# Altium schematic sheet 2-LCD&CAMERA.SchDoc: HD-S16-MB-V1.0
size A4
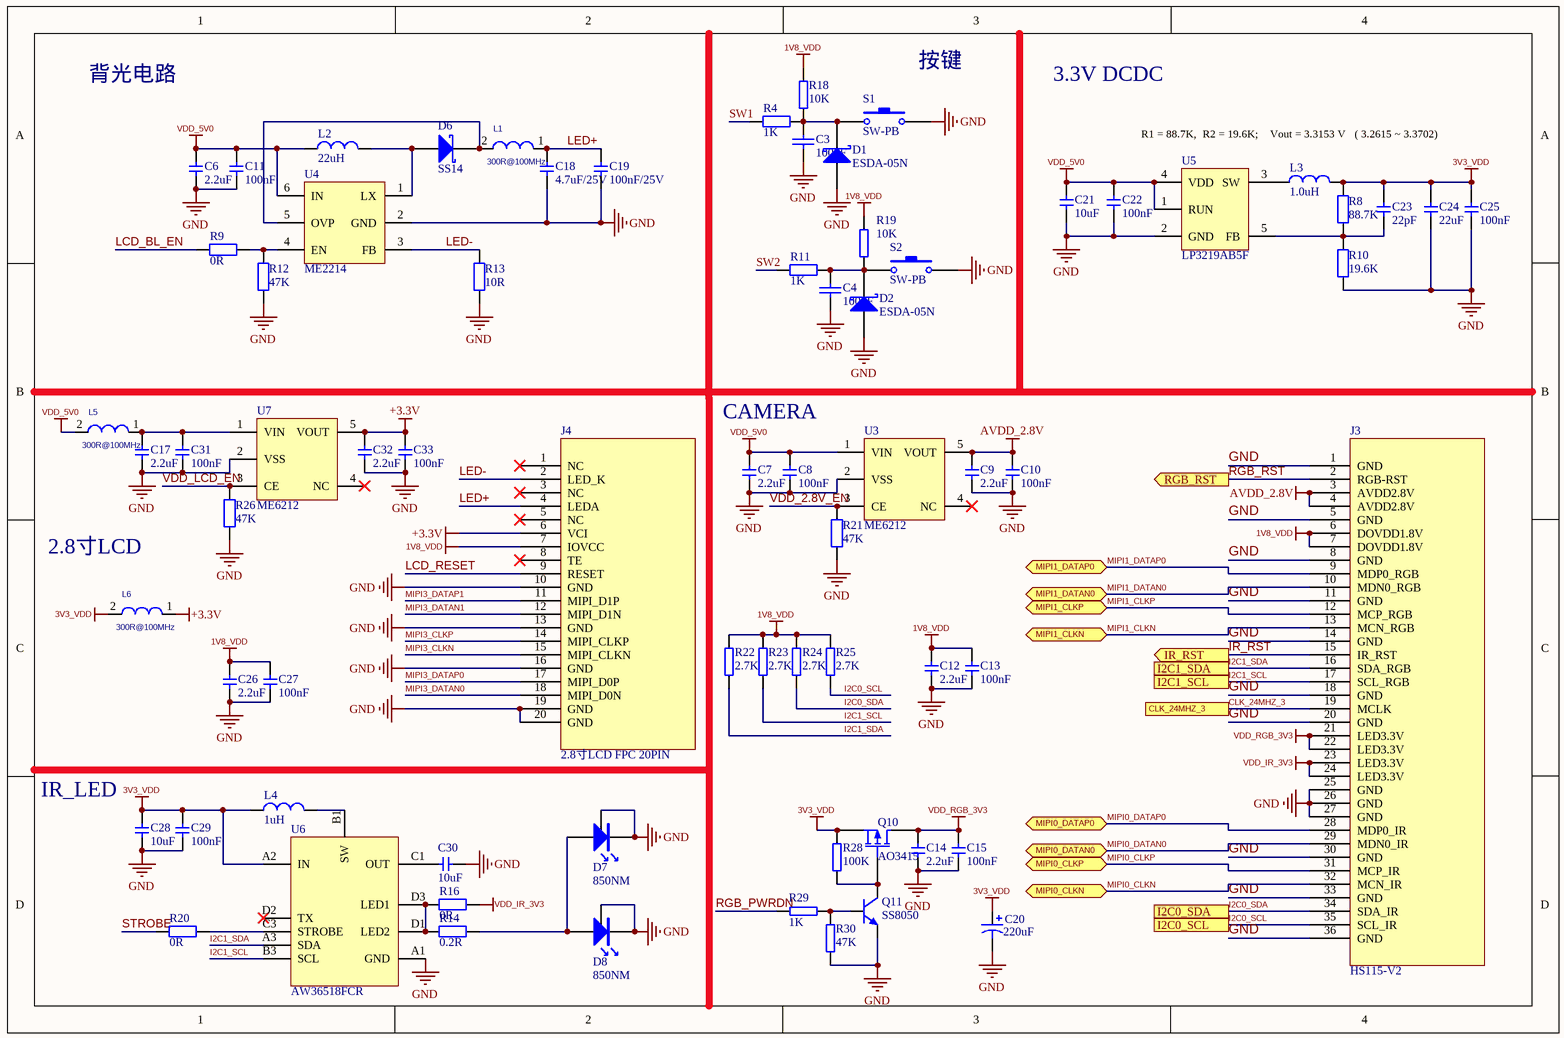
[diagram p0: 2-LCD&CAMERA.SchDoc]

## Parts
C3  100nF  [C0402]
C4  100nF  [C0402]
C6  2.2uF  [C0402]
C7  2.2uF  [C0402]
C8  100nF  [C0402]
C9  2.2uF  [C0402]
C10  100nF  [C0402]
C11  100nF  [C0402]
C12  2.2uF  [C0402]
C13  100nF  [C0402]
C14  2.2uF  [C0402]
C15  100nF  [C0402]
C17  2.2uF  [C0402]
C18  4.7uF/25V  [Cap_0603]
C19  100nF/25V  [C0402]
C20  value 220uF  [SMD,6.3x7.7mm]  (hidden comment: Cap Pol1)
C21  10uF  [Cap_0603]
C22  100nF  [C0402]
C23  22pF  [C0402]
C24  22uF  [CAP_0603]
C25  100nF  [C0402]
C26  2.2uF  [C0402]
C27  100nF  [C0402]
C28  10uF  [C0402]
C29  100nF  [C0402]
C30  10uF  [C0402]
C31  100nF  [C0402]
C32  2.2uF  [C0402]
C33  100nF  [C0402]
D1  ESDA-05N  [R0402]
D2  ESDA-05N  [R0402]
D6  SS14  [SOD-123F]
D7  850NM  [LED-3535-850MM]
D8  850NM  [LED-3535-850MM]
J3  HS115-V2  [0.5-36PIN]
J4  2.8寸LCD FPC 20PIN  [0.5-20PIN-抽屉上接]
L1  300R@100MHz  [Res_0603]
L2  22uH  [L3*3]
L3  1.0uH  [L2.5x2.0x1.0mm]
L4  1uH  [L2.5x2.0x1.0mm]
L5  300R@100MHz  [Res_0603]
L6  300R@100MHz  [Res_0603]
Q10  AO3415  [SOT-23]
Q11  SS8050  [SOT23-BEC]
R4  1K  [R0402]
R8  88.7K  [R0402]
R9  0R  [R0402]
R10  19.6K  [R0402]
R11  1K  [R0402]
R12  47K  [R0402]
R13  10R  [R0805]
R14  0.2R  [R0805]
R16  0R  [R0805]
R18  10K  [R0402]
R19  10K  [R0402]
R20  0R  [R0402]
R21  47K  [R0402]
R22  2.7K  [R0402]
R23  2.7K  [R0402]
R24  2.7K  [R0402]
R25  2.7K  [R0402]
R26  47K  [R0402]
R28  100K  [R0402]
R29  1K  [R0402]
R30  47K  [R0402]
S1  SW-PB  [轻触开关4.5x4.5]
S2  SW-PB  [轻触开关4.5x4.5]
U3  ME6212  [SOT23-5]
U4  ME2214  [SOT26]
U5  LP3219AB5F  [SOT23-5]
U6  AW36518FCR  [FCQFN-10L]
U7  ME6212  [SOT23-5]

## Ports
CLK_24MHZ_3, I2C0_SCL, I2C0_SDA, I2C1_SCL, I2C1_SDA, IR_RST (out), MIPI0_CLKN (bidir), MIPI0_CLKP (bidir), MIPI0_DATAN0 (bidir), MIPI0_DATAP0 (bidir), MIPI1_CLKN (bidir), MIPI1_CLKP (bidir), MIPI1_DATAN0 (bidir), MIPI1_DATAP0 (bidir), RGB_RST (out)

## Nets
1V8_VDD: C12.1 C13.1 C26.1 C27.1 J3.6(DOVDD1.8V) J3.7(DOVDD1.8V) J4.7(IOVCC) R18.2 R19.2 R22.1 R23.1 R24.1 R25.1
3V3_VDD: C20.1 C23.2 C24.1 C25.1 C28.1 C29.1 L3.2 L4.1 L6.2 Q10.2(S) R8.2 R28.2 U6.A2(IN)
+3.3V: C32.1 C33.1 J4.6(VCI) L6.1 U7.5(VOUT)
AVDD_2.8V: C9.1 C10.1 J3.3(AVDD2.8V) J3.4(AVDD2.8V) U3.5(VOUT)
GND: C3.2 C4.2 C6.2 C7.2 C8.2 C9.2 C10.2 C11.2 C12.2 C13.2 C14.2 C15.2 C17.2 C18.2 C19.2 C20.2 C21.2 C22.2 C24.2 C25.2 C26.2 C27.2 C28.2 C29.2 C30.2 C31.2 C32.2 C33.2 D1.1(A) D2.1(A) D7.0 D7.K D8.0 D8.K J3.1(GND) J3.5(GND) J3.8(GND) J3.11(GND) J3.14(GND) J3.18(GND) J3.20(GND) J3.25(GND) J3.26(GND) J3.27(GND) J3.30(GND) J3.33(GND) J3.36(GND) J4.10(GND) J4.13(GND) J4.16(GND) J4.19(GND) J4.20(GND) Q11.E R10.2 R12.1 R13.2 R21.1 R26.1 R30.2 S1.2 S2.2 U3.2(VSS) U4.2(GND) U5.2(GND) U6.A1(GND) U7.2(VSS)
VDD_5V0: C6.1 C7.1 C8.1 C11.1 C21.1 C22.1 L2.1 L5.2 U3.1(VIN) U4.6(IN) U5.1(RUN) U5.4(VDD)
VDD_IR_3V3: J3.23(LED3.3V) J3.24(LED3.3V) R16.2
VDD_RGB_3V3: C14.1 C15.1 J3.21(LED3.3V) J3.22(LED3.3V) Q10.3(D)
CLK_24MHZ_3: J3.19(MCLK) ; port CLK_24MHZ_3
I2C0_SCL: J3.35(SCL_IR) R25.2 ; port I2C0_SCL
I2C0_SDA: J3.34(SDA_IR) R24.2 ; port I2C0_SDA
I2C1_SCL: J3.17(SCL_RGB) R23.2 U6.B3(SCL) ; port I2C1_SCL
I2C1_SDA: J3.16(SDA_RGB) R22.2 U6.A3(SDA) ; port I2C1_SDA
IR_RST: J3.15(IR_RST) ; port IR_RST
LCD_BL_EN: R9.1
LCD_RESET: J4.9(RESET)
LED+: C18.1 C19.1 J4.4(LEDA) L1.1
LED-: J4.2(LED_K) R13.1 U4.3(FB)
MIPI0_CLKN: J3.32(MCN_IR) ; port MIPI0_CLKN
MIPI0_CLKP: J3.31(MCP_IR) ; port MIPI0_CLKP
MIPI0_DATAN0: J3.29(MDN0_IR) ; port MIPI0_DATAN0
MIPI0_DATAP0: J3.28(MDP0_IR) ; port MIPI0_DATAP0
MIPI1_CLKN: J3.13(MCN_RGB) ; port MIPI1_CLKN
MIPI1_CLKP: J3.12(MCP_RGB) ; port MIPI1_CLKP
MIPI1_DATAN0: J3.10(MDN0_RGB) ; port MIPI1_DATAN0
MIPI1_DATAP0: J3.9(MDP0_RGB) ; port MIPI1_DATAP0
MIPI3_CLKN: J4.15(MIPI_CLKN)
MIPI3_CLKP: J4.14(MIPI_CLKP)
MIPI3_DATAN0: J4.18(MIPI_D0N)
MIPI3_DATAN1: J4.12(MIPI_D1N)
MIPI3_DATAP0: J4.17(MIPI_D0P)
MIPI3_DATAP1: J4.11(MIPI_D1P)
RGB_PWRDN: R29.2
RGB_RST: J3.2(RGB-RST) ; port RGB_RST
STROBE: R20.1
SW1: R4.1
SW2: R11.1
VDD_2.8V_EN: R21.2 U3.3(CE)
VDD_LCD_EN: R26.2 U7.3(CE)
NetC3_1: C3.1 D1.2(K) R4.2 R18.1 S1.1
NetC4_1: C4.1 D2.2(K) R11.2 R19.1 S2.1
NetC17_1: C17.1 C31.1 L5.1 U7.1(VIN)
NetC23_1: C23.1 R8.1 R10.1 U5.5(FB)
NetC30_1: C30.1 U6.C1(OUT)
NetD6_1: D6.1(A) L2.2 U4.1(LX)
NetD6_2: D6.2(K) L1.2 U4.5(OVP)
NetD7_A: D7.A D8.A R14.2
NetL3_1: L3.1 U5.3(SW)
NetL4_2: L4.2 U6.B1(SW)
NetQ10_1: Q10.1(G) Q11.C R28.1
NetQ11_B: Q11.B R29.1 R30.1
NetR9_2: R9.2 R12.2 U4.4(EN)
NetR14_1: R14.1 R16.1 U6.D1(LED2) U6.D3(LED1)
NetR20_2: R20.2 U6.C3(STROBE)

Not connected (* = marked no-connect by the designer): J4 1(NC)* 3(NC)* 5(NC)* 8(TE)*; U3 4(NC)*; U6 D2(TX)*; U7 4(NC)*

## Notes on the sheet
- 背光电路
- (near S1) 按键
- 3.3V DCDC
- R1 = 88.7K,  R2 = 19.6K;    Vout = 3.3153 V   ( 3.2615 ~ 3.3702)
- CAMERA
- 2.8寸LCD
- (near C28) IR_LED

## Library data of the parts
C3 C4 = Cap: Capacitor; 物料名称: 贴片电容; 物料编码: 3.01.04.0056
C6-C15 C17-C19 C21-C33 = CAP1: C?
C20 = Cap Pol1: Polarized Capacitor (Radial)
D1 D2 D6 = Diode BAS70: Silicon AF Schottky Diode for High-Speed Switching; Note: Pin 2 is not connected and not drawn.
D7 D8 = LED_IR: 贴片LED，3535，红外850NM
J4 = 2.8寸LCD FPC 20PIN: 1-Lane MIPI
L1 L5 L6 = L/0402
L2-L4 = LineInductors
Q11 = NPN: 贴片三极管
R4 R8-R14 R16 R20 R21 R26 = Res2: Resistor
R18 R19 R22-R25 R28-R30 = RES1: R?
S1 S2 = SW-PB: Switch
U5 = TD6817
